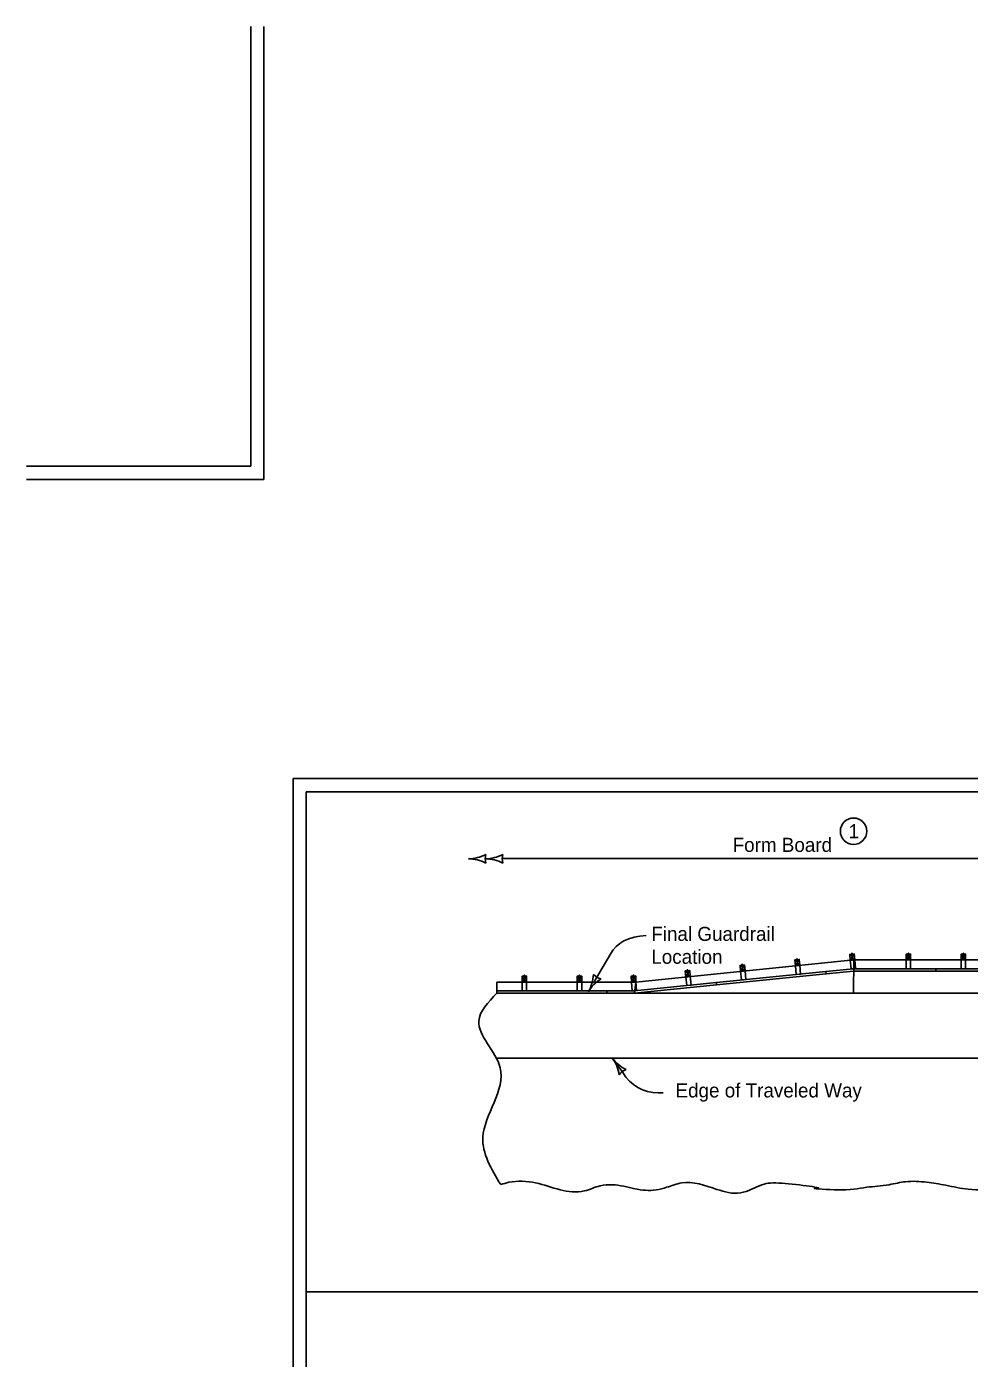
# Model space of a CAD drawing. Extents: x 9538 to 81668, y 7600 to 11751.
# Drawn here: x 24230 to 25301, y 9286 to 10798 of the extents above; entities that cross this region are included whole.
import ezdxf

# ---------------------------------------------------------------- set-up
doc = ezdxf.new("R2010")
doc.units = 0
for name, color, linetype in [('Default', 7, 'Continuous'), ('DsnShtMinorGrid13', 7, 'Continuous'), ('DsnShtMinorGrid14', 7, 'Continuous'), ('dsnStdDimension', 7, 'Continuous'), ('dsnStdNameDate', 7, 'Continuous'), ('dsnStdNote', 7, 'Continuous'), ('dsnStdShading', 7, 'Continuous'), ('dsnStdTable', 7, 'Continuous')]:
    doc.layers.add(name, color=color, linetype=linetype)

msp = doc.modelspace()

# ---------------------------------------------------------------- linework, layer by layer
at = {"layer": 'Default'}
msp.add_lwpolyline([(24532.5, 9944), (27667.6, 9944), (27667.6, 7924), (24532.5, 7924)], close=True, dxfattribs=at)
at = {"layer": 'DsnShtMinorGrid13'}
msp.add_circle((25169.2, 9884.3), 15, dxfattribs=at)
at = {"layer": 'DsnShtMinorGrid14'}
for p, q in [((25164.9, 9744.4), (25170.5, 9738.3)), ((25169.8, 9744.9), (25165.5, 9737.8)), ((25167.3, 9745.6), (25167.2, 9745.7)), ((25168, 9738), (25167.4, 9744.7)), ((25229, 9744.7), (25234, 9738.1)), ((25234, 9744.7), (25229, 9738.1)), ((25231.5, 9745.7), (25231.5, 9745.8)), ((25231.5, 9738.1), (25231.5, 9744.7)), ((25291.5, 9744.7), (25296.5, 9738.1)), ((25296.5, 9744.7), (25291.5, 9738.1)), ((25294, 9745.7), (25294, 9745.8)), ((25294, 9738.1), (25294, 9744.7)), ((24983, 9726.2), (24978.7, 9719)), ((24980.4, 9726.9), (24980.4, 9727)), ((25040.2, 9731.9), (25045.9, 9725.8)), ((25045.2, 9732.4), (25040.9, 9725.3)), ((25042.6, 9733.1), (25042.6, 9733.2)), ((25043.4, 9725.5), (25042.7, 9732.1)), ((25102.4, 9738.1), (25108, 9732)), ((25107.4, 9738.6), (25103.1, 9731.5)), ((25103.1, 9731.5), (25108, 9732)), ((25104.1, 9721.5), (25103.1, 9731.5)), ((25104.8, 9739.4), (25104.8, 9739.4)), ((25105.6, 9731.8), (25104.9, 9738.4)), ((25108, 9732), (25109, 9722)), ((25169, 9728.1), (25137.6, 9724.9)), ((25165.5, 9737.8), (25170.5, 9738.3)), ((25168, 9738), (25165.5, 9737.8)), ((25168, 9738), (25165.5, 9737.8)), ((25166.5, 9727.8), (25165.5, 9737.8)), ((25171.5, 9728.3), (25166.5, 9727.8)), ((25169, 9728.1), (25262.8, 9728.1)), ((25170.5, 9738.3), (25171.5, 9728.3)), ((25229, 9738.1), (25234, 9738.1)), ((25229, 9728.1), (25229, 9738.1)), ((25234, 9728.1), (25229, 9728.1)), ((25234, 9738.1), (25234, 9728.1)), ((25262.8, 9725.4), (25262.8, 9728.1)), ((25262.8, 9728.1), (25335, 9728.1)), ((25262.8, 9725.4), (25262.8, 9728.1)), ((25291.5, 9738.1), (25296.5, 9738.1)), ((25291.5, 9728.1), (25291.5, 9738.1)), ((25296.5, 9728.1), (25291.5, 9728.1)), ((25296.5, 9738.1), (25296.5, 9728.1)), ((24792.8, 9719.7), (24797.8, 9713)), ((24797.8, 9719.7), (24792.8, 9713)), ((24792.8, 9713), (24797.8, 9713)), ((24792.8, 9703), (24792.8, 9713)), ((24795.3, 9720.6), (24795.3, 9720.7)), ((24795.3, 9713), (24795.3, 9719.7)), ((24797.8, 9713), (24797.8, 9703)), ((24855.3, 9719.7), (24860.3, 9713)), ((24860.3, 9719.7), (24855.3, 9713)), ((24855.3, 9713), (24860.3, 9713)), ((24855.3, 9703), (24855.3, 9713)), ((24857.8, 9720.6), (24857.8, 9720.7)), ((24857.8, 9713), (24857.8, 9719.7)), ((24860.3, 9713), (24860.3, 9703)), ((24916.7, 9719.7), (24922, 9713.3)), ((24921.7, 9720), (24917, 9713)), ((24917, 9713), (24922, 9713.3)), ((24917.5, 9703), (24917, 9713)), ((24919.1, 9720.8), (24919.1, 9720.9)), ((24919.5, 9713.2), (24919.2, 9719.9)), ((24920, 9703), (25013.3, 9712.4)), ((24922, 9713.3), (24922.5, 9703.2)), ((24978, 9725.7), (24983.7, 9719.5)), ((24978.7, 9719), (24983.7, 9719.5)), ((24979.7, 9709), (24978.7, 9719)), ((24981.2, 9719.3), (24980.5, 9725.9)), ((24983.7, 9719.5), (24984.7, 9709.5)), ((25013.3, 9712.4), (25137.6, 9724.9)), ((25013.5, 9709.7), (25013.3, 9712.4)), ((25013.5, 9709.7), (25013.3, 9712.4)), ((25013.5, 9709.7), (25137.9, 9722.2)), ((25040.9, 9725.3), (25045.9, 9725.8)), ((25041.9, 9715.3), (25040.9, 9725.3)), ((25046.9, 9715.8), (25041.9, 9715.3)), ((25045.9, 9725.8), (25046.9, 9715.8)), ((25109, 9722), (25104.1, 9721.5)), ((25137.9, 9722.2), (25137.6, 9724.9)), ((25137.9, 9722.2), (25137.6, 9724.9)), ((25169, 9725.4), (25137.9, 9722.2)), ((25169, 9725.4), (25262.8, 9725.4)), ((25262.8, 9725.4), (25335, 9725.4)), ((24764, 9703), (24889, 9703)), ((24764, 9700.3), (24764, 9703)), ((24764, 9700.3), (24889, 9700.3)), ((24797.8, 9703), (24792.8, 9703)), ((24860.3, 9703), (24855.3, 9703)), ((24889, 9703), (24920, 9703)), ((24889, 9700.3), (24889, 9703)), ((24889, 9700.3), (24920.3, 9700.3)), ((24922.5, 9703.2), (24917.5, 9703)), ((24920.3, 9700.3), (25013.5, 9709.7)), ((24984.7, 9709.5), (24979.7, 9709))]:
    msp.add_line(p, q, dxfattribs=at)
for points in [[(25165.5, 9737.8), (25170.5, 9738.3), (25169.8, 9744.9), (25164.9, 9744.4)], [(25229, 9738.1), (25234, 9738.1), (25234, 9744.7), (25229, 9744.7)], [(25291.5, 9738.1), (25296.5, 9738.1), (25296.5, 9744.7), (25291.5, 9744.7)], [(24978.7, 9719), (24983.7, 9719.5), (24983, 9726.2), (24978, 9725.7)], [(25040.9, 9725.3), (25045.9, 9725.8), (25045.2, 9732.4), (25040.2, 9731.9)], [(25103.1, 9731.5), (25108, 9732), (25107.4, 9738.6), (25102.4, 9738.1)], [(24792.8, 9713), (24797.8, 9713), (24797.8, 9719.7), (24792.8, 9719.7)], [(24855.3, 9713), (24860.3, 9713), (24860.3, 9719.7), (24855.3, 9719.7)], [(24917, 9713), (24922, 9713.3), (24921.7, 9720), (24916.7, 9719.7)]]:
    msp.add_lwpolyline(points, close=True, dxfattribs=at)
for points in [[(25167, 9744.6), (25167, 9745.1), (25167.6, 9745.1), (25167.7, 9744.7)], [(25167.1, 9745.1), (25167.1, 9745.6), (25167.4, 9745.7), (25167.5, 9745.1)], [(25231.2, 9744.7), (25231.2, 9745.2), (25231.8, 9745.2), (25231.8, 9744.7)], [(25231.3, 9745.2), (25231.3, 9745.7), (25231.7, 9745.7), (25231.7, 9745.2)], [(25293.7, 9744.7), (25293.7, 9745.2), (25294.3, 9745.2), (25294.3, 9744.7)], [(25293.8, 9745.2), (25293.8, 9745.7), (25294.2, 9745.7), (25294.2, 9745.2)], [(24980.2, 9725.9), (24980.1, 9726.3), (24980.8, 9726.4), (24980.9, 9726)], [(24980.3, 9726.3), (24980.2, 9726.9), (24980.6, 9726.9), (24980.7, 9726.4)], [(25042.4, 9732.1), (25042.3, 9732.5), (25043, 9732.6), (25043, 9732.2)], [(25042.5, 9732.5), (25042.4, 9733.1), (25042.8, 9733.1), (25042.8, 9732.6)], [(25104.6, 9738.4), (25104.5, 9738.8), (25105.2, 9738.8), (25105.2, 9738.4)], [(25104.6, 9738.8), (25104.6, 9739.3), (25105, 9739.4), (25105, 9738.8)], [(24794.9, 9719.7), (24794.9, 9720.1), (24795.6, 9720.1), (24795.6, 9719.7)], [(24795.1, 9720.1), (24795.1, 9720.6), (24795.5, 9720.6), (24795.5, 9720.1)], [(24857.4, 9719.7), (24857.4, 9720.1), (24858.1, 9720.1), (24858.1, 9719.7)], [(24857.6, 9720.1), (24857.6, 9720.6), (24858, 9720.6), (24858, 9720.1)], [(24919.5, 9713.2), (24917, 9713), (24917, 9713)], [(24918.8, 9719.8), (24918.8, 9720.3), (24919.5, 9720.3), (24919.5, 9719.9)], [(24918.9, 9720.3), (24918.9, 9720.8), (24919.3, 9720.8), (24919.3, 9720.3)]]:
    msp.add_lwpolyline(points, dxfattribs=at)
at = {"layer": 'dsnStdDimension'}
for p, q in [((24770.8, 9853.2), (25793.2, 9853.2)), ((25103.1, 9731.5), (24921.8, 9713)), ((25169.5, 9738.1), (25103.1, 9731.5)), ((25103.1, 9731.5), (25103.1, 9731.5)), ((25169.5, 9738.1), (25169.2, 9700.3)), ((25169.2, 9700.3), (25169.5, 9738.1)), ((25420.8, 9738.1), (25169.5, 9738.1)), ((25169.5, 9738.1), (25169.5, 9738.1)), ((24764, 9713), (24764, 9700.3)), ((24921.8, 9713), (24764, 9713)), ((24921.8, 9713), (24920.3, 9700.3)), ((24920.3, 9700.3), (24921.8, 9713)), ((24921.8, 9713), (24921.8, 9713)), ((24921.8, 9713), (24921.8, 9713)), ((24764, 9700.3), (24920.3, 9700.3)), ((24920.3, 9700.3), (25169.2, 9700.3)), ((25169.2, 9700.3), (26200.9, 9700.3))]:
    msp.add_line(p, q, dxfattribs=at)
for centre, radius, start, end in [((24731.6, 9895.5), 42.5, 270, 298.0725), ((24731.6, 9810.5), 42.5, 61.9275, 90), ((24750.8, 9895.5), 42.5, 270, 298.0725), ((24767.2, 9853), 16.4, 162.2666, 197.7334), ((24750.8, 9810.5), 42.5, 61.9275, 90), ((24786.5, 9853), 16.4, 162.2666, 197.7334)]:
    msp.add_arc(centre, radius, start, end, dxfattribs=at)
at = {"layer": 'dsnStdNameDate'}
msp.add_line((26703.1, 9361), (24547.5, 9361), dxfattribs=at)
at = {"layer": 'dsnStdNote'}
for p, q in [((24893.5, 9745.4), (24875, 9714)), ((24907.1, 9610.2), (24895, 9626.7)), ((24947.2, 9587.1), (24952.7, 9587.1))]:
    msp.add_line(p, q, dxfattribs=at)
for centre, radius, start, end in [((24831.2, 9723.5), 42.5, 329.3797, 357.4522), ((24904.4, 9680.2), 42.5, 121.3072, 149.3797), ((24885.9, 9732.6), 16.4, 221.6464, 257.1131), ((24929.3, 9651.9), 42.5, 216.3726, 244.445), ((24860.8, 9601.5), 42.5, 8.3001, 36.3726), ((24916.2, 9598), 16.4, 108.6392, 144.1059), ((24947.3, 9633.6), 46.5, 210.2274, 270)]:
    msp.add_arc(centre, radius, start, end, dxfattribs=at)
msp.add_ellipse((24974.6, 9706.3), major_axis=(-81.1, 39), ratio=0.555556, start_param=5.482641, end_param=6.283185, dxfattribs=at)
at = {"layer": 'dsnStdShading'}
for q in [(24547.5, 8319), (27643.2, 9929)]:
    msp.add_line((24547.5, 9929), q, dxfattribs=at)
at = {"layer": 'dsnStdTable'}
for p, q in [((24484.3, 10298.9), (24484.3, 10798.2)), ((24499.3, 10283.9), (24499.3, 10798.2)), ((24484.3, 10298.9), (24229.8, 10298.9)), ((24499.3, 10283.9), (24229.8, 10283.9)), ((24921.8, 9713), (25169.5, 9738.1)), ((25417.4, 9738.1), (25169.5, 9738.1)), ((24921.8, 9713), (24764, 9713)), ((24764, 9713), (24764, 9703)), ((24764, 9700.3), (26377.7, 9700.3)), ((24764.2, 9626.7), (26378, 9626.7))]:
    msp.add_line(p, q, dxfattribs=at)
for points in [[(24764, 9700.3), (24743.4, 9668.7), (24767.7, 9615.7), (24748, 9536.6), (24768.3, 9482.9)], [(24768.3, 9482.9), (24777.7, 9485.5), (24808, 9484.9), (24835.9, 9477), (24863.3, 9475.8), (24881.5, 9481.5), (24908.3, 9481), (24932.8, 9476.4), (24956.8, 9479.8), (24973.9, 9484.9), (25013.8, 9477.5), (25040.6, 9473.5), (25065.1, 9482.7), (25087.9, 9484.4), (25126.7, 9478.7), (25126.1, 9478.7), (25147.3, 9477.1), (25184.4, 9479.9), (25209.5, 9482.8), (25228.3, 9486.2), (25252.2, 9485.6), (25273.9, 9482.2), (25299.5, 9477.6), (25333.2, 9478.8), (25364.6, 9485.1), (25389.6, 9485.1), (25421.6, 9477.6), (25450.7, 9474.8), (25484.3, 9481.6), (25516.8, 9485.1), (25551, 9478.2), (25576.7, 9475.4), (25598.9, 9478.8), (25626.9, 9494.2), (25637.1, 9496.5), (25661.6, 9498.7), (25692.3, 9499.3), (25713.4, 9499.3), (25766.7, 9490)]]:
    msp.add_spline(points, degree=3, dxfattribs=at)

# ---------------------------------------------------------------- texts
at = {"layer": 'DsnShtMinorGrid13'}
msp.add_text('1', height=16, dxfattribs=at).set_placement((25163.6, 9876.3))
at = {"layer": 'dsnStdDimension'}
msp.add_text('Form Board', height=16, dxfattribs=at).set_placement((25031.8, 9860.8))
at = {"layer": 'dsnStdNote'}
for s, p in [('Final Guardrail ', (24939.4, 9759.7)), ('Location', (24939.4, 9733.7)), ('Edge of Traveled Way', (24966.9, 9581.9))]:
    msp.add_text(s, height=16, dxfattribs=at).set_placement(p)

doc.saveas('drawing.dxf')
